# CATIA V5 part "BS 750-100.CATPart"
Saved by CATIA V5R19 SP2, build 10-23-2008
Part number: BS 750-100
Bounding box of the stored display mesh (mm): x -22.494 to 22.494, y -22.494 to 22.494, z 0 to 232
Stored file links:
  C:\Users\Bora\Desktop\3D Katı model\BS serisi\BS 750\BS 750-100.CATPart
  C:\Program Files\Dassault Systemes\B19\intel_a\reffiles\standard\MetricThickPitch.txt
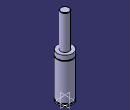
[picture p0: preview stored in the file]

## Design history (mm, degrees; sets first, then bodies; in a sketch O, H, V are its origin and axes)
Body1 (main body)
  Sketch1 on yz-plane, origin (0, 0, 0), H (0, 1, 0), V (0, 0, 1)
    point P3 (12.5, 231)
    point P5 (12.5, 231)
    point P7 (22.5, 117.5)
    point P8 (22.5, 115.5)
    point P12 (22.5, 115.5)
    point P13 (22.5, 117.5)
    line L1 (22.5, 0) -> (22.5, 4)
    line L2 (12.5, 231) -> (12.5, 131)
    arc A1 centre (11.5, 231) radius 1 from (12.5, 231) to (11.5, 232) ccw
    arc A2 centre (22.5, 116.5) radius 1 from (22.5, 117.5) to (22.5, 115.5) ccw
    line L3 (20, 7.5) -> (20, 4)
    line L4 (22.5, 7.5) -> (22.5, 115.5)
    line L5 (22.5, 117.5) -> (22.5, 131)
    line L6 (11.5, 232) -> (0, 232)
    point P15 (0, 232)
    line L7 (12.5, 131) -> (22.5, 131)
    line L8 (0, 0) -> (22.5, 0)
    line L9 (20, 7.5) -> (22.5, 7.5)
    line L10 (20, 4) -> (22.5, 4)
    coincidence: P15 V, P3 P5, P7 P13, P8 P12
    tangency: L6 A1
    horizontal: L7 H, L8 H, L9 H, L10 H
  Shaft1: profile Sketch1, axis Sketch1.V, angle 360
  Sketch2 on face of Shaft1 from Sketch1.L8, origin (0, 0, 0), H (1, 0, 0), V (0, -1, 0)
    point P1 (10, 0)
    distance P1 V = 10
  Hole1: placed by Sketch2, at (10, 0, 0) direction (0, 0, 1), diameter 6.647, depth 4, threaded "M8", thread diameter 8, thread depth 4, pitch 1.25
  CircPattern1: of Hole1, instances 2, angular step 180, axis from xy-plane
